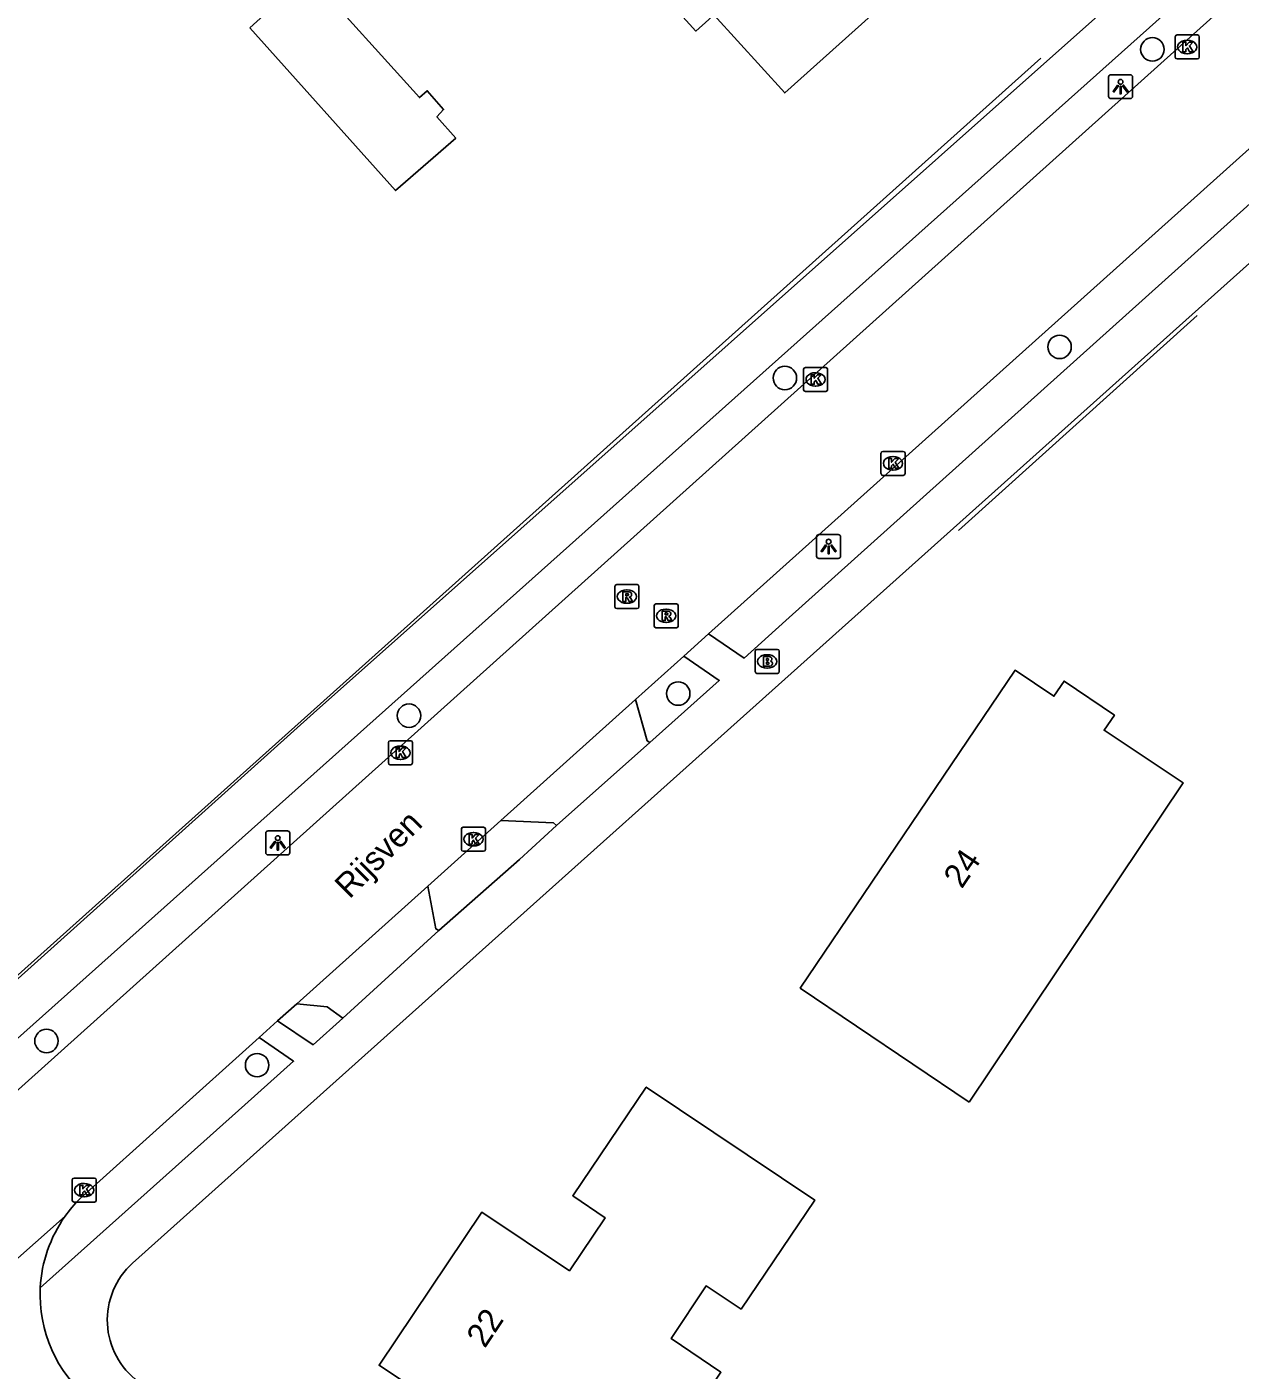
# Model space of a CAD drawing. Extents: x 163268 to 164360, y 381529 to 382285.
# Drawn here: x 163948.5 to 163999, y 381682.3 to 381738.3 of the extents above; entities that cross this region are included whole.
import ezdxf

# ---------------------------------------------------------------- set-up
doc = ezdxf.new("R2010")
doc.units = 0
for name, color, linetype in [('IMGEO_Boom', 7, 'Continuous'), ('IMGEO_Brandkraan', 7, 'Continuous'), ('IMGEO_Hek', 7, 'Continuous'), ('IMGEO_Kolk', 7, 'Continuous'), ('IMGEO_Lichtpunt', 7, 'Continuous'), ('IMGEO_Openbare_ruimte_label', 7, 'Continuous'), ('IMGEO_Pand', 7, 'Continuous'), ('IMGEO_Pand_nummerreeks', 7, 'Continuous'), ('IMGEO_Rijbaan_lokaal_open', 7, 'Continuous'), ('IMGEO_Rioolput', 7, 'Continuous'), ('IMGEO_Voetpad_open', 7, 'Continuous')]:
    doc.layers.add(name, color=color, linetype=linetype)

msp = doc.modelspace()

# ---------------------------------------------------------------- linework, layer by layer
at = {"layer": 'IMGEO_Boom'}
for centre in [(163995.384, 381737.33), (163991.517, 381724.931), (163980.071, 381723.636), (163975.628, 381710.482), (163964.412, 381709.563), (163949.308, 381696.004), (163958.082, 381694.996)]:
    msp.add_circle(centre, 0.489, dxfattribs=at)
at = {"layer": 'IMGEO_Brandkraan'}
for p, q in [((163978.835, 381711.397), (163978.835, 381712.249)), ((163978.91, 381712.323), (163979.762, 381712.323)), ((163979.323, 381712.103), (163979.348, 381712.103)), ((163979.836, 381712.249), (163979.836, 381711.397)), ((163979.346, 381711.543), (163979.321, 381711.543)), ((163979.762, 381711.323), (163978.91, 381711.323))]:
    msp.add_line(p, q, dxfattribs=at)
for points in [[(163978.835, 381711.397), (163978.835, 381712.249)], [(163978.91, 381712.323), (163979.762, 381712.323)], [(163979.183, 381712.023), (163979.183, 381711.623), (163979.396, 381711.623)], [(163979.414, 381712.023), (163979.183, 381712.023)], [(163979.836, 381712.249), (163979.836, 381711.397)], [(163979.362, 381711.942), (163979.308, 381711.942), (163979.308, 381711.866)], [(163979.308, 381711.866), (163979.361, 381711.866)], [(163979.37, 381711.79), (163979.308, 381711.79), (163979.308, 381711.709)], [(163979.308, 381711.709), (163979.37, 381711.709)], [(163979.762, 381711.323), (163978.91, 381711.323)]]:
    msp.add_lwpolyline(points, dxfattribs=at)
for centre, radius, start, end in [((163978.912, 381712.247), 0.0765, 91.552, 178.448), ((163978.912, 381712.247), 0.0765, 91.552, 178.448), ((163979.418, 381711.878), 0.145, 59.4692, 91.5367), ((163979.443, 381711.925), 0.0922, 285.5137, 58.1501), ((163979.76, 381712.247), 0.0765, 1.552, 88.448), ((163979.76, 381712.247), 0.0765, 1.552, 88.448), ((163978.912, 381711.399), 0.0765, 181.552, 268.448), ((163978.912, 381711.399), 0.0765, 181.552, 268.448), ((163979.363, 381711.904), 0.0379, 267.8285, 90.9355), ((163979.371, 381711.749), 0.0404, 269.8759, 90.5077), ((163979.402, 381711.874), 0.251, 268.6676, 293.5347), ((163979.448, 381711.733), 0.105, 301.3115, 78.989), ((163979.76, 381711.399), 0.0765, 271.552, 358.448), ((163979.76, 381711.399), 0.0765, 271.552, 358.448)]:
    msp.add_arc(centre, radius, start, end, dxfattribs=at)
for centre, major_axis, ratio, start_param, end_param in [((163979.322, 381711.823), (-0.387, 0.002), 0.722429, 4.712389, 7.853982), ((163979.347, 381711.823), (-0.39, 0.002), 0.717154, 1.570796, 4.712389)]:
    msp.add_ellipse(centre, major_axis=major_axis, ratio=ratio, start_param=start_param, end_param=end_param, dxfattribs=at)
at = {"layer": 'IMGEO_Hek'}
for points in [[(163924.002, 381677.14), (163990.733, 381736.967)], [(163987.306, 381717.275), (163997.245, 381726.234)]]:
    msp.add_lwpolyline(points, dxfattribs=at)
at = {"layer": 'IMGEO_Kolk'}
for p, q in [((163996.335, 381737.004), (163996.335, 381737.856)), ((163996.41, 381737.93), (163997.262, 381737.93)), ((163996.823, 381737.71), (163996.848, 381737.71)), ((163997.336, 381737.856), (163997.336, 381737.004)), ((163996.846, 381737.15), (163996.821, 381737.15)), ((163997.262, 381736.93), (163996.41, 381736.93)), ((163980.852, 381723.147), (163980.852, 381723.999)), ((163980.927, 381724.073), (163981.779, 381724.073)), ((163981.34, 381723.853), (163981.365, 381723.853)), ((163981.853, 381723.999), (163981.853, 381723.147)), ((163981.363, 381723.293), (163981.338, 381723.293)), ((163981.779, 381723.073), (163980.927, 381723.073)), ((163984.076, 381719.651), (163984.076, 381720.503)), ((163984.151, 381720.577), (163985.003, 381720.577)), ((163984.564, 381720.357), (163984.589, 381720.357)), ((163985.077, 381720.503), (163985.077, 381719.651)), ((163984.587, 381719.797), (163984.562, 381719.797)), ((163985.003, 381719.577), (163984.151, 381719.577)), ((163963.554, 381707.59), (163963.554, 381708.442)), ((163963.629, 381708.516), (163964.481, 381708.516)), ((163964.042, 381708.296), (163964.067, 381708.296)), ((163964.555, 381708.442), (163964.555, 381707.59)), ((163964.481, 381707.516), (163963.629, 381707.516)), ((163964.065, 381707.736), (163964.04, 381707.736)), ((163966.594, 381703.987), (163966.594, 381704.839)), ((163966.669, 381704.913), (163967.521, 381704.913)), ((163967.082, 381704.693), (163967.107, 381704.693)), ((163967.595, 381704.839), (163967.595, 381703.987)), ((163967.105, 381704.133), (163967.08, 381704.133)), ((163967.521, 381703.913), (163966.669, 381703.913)), ((163950.38, 381689.362), (163950.38, 381690.214)), ((163950.455, 381690.288), (163951.307, 381690.288)), ((163951.381, 381690.214), (163951.381, 381689.362)), ((163950.868, 381690.068), (163950.893, 381690.068)), ((163951.307, 381689.288), (163950.455, 381689.288)), ((163950.891, 381689.508), (163950.866, 381689.508))]:
    msp.add_line(p, q, dxfattribs=at)
for points in [[(163996.335, 381737.004), (163996.335, 381737.856)], [(163996.41, 381737.93), (163997.262, 381737.93)], [(163997.336, 381737.856), (163997.336, 381737.004)], [(163996.656, 381737.63), (163996.779, 381737.63), (163996.779, 381737.479), (163996.909, 381737.63), (163997.073, 381737.63), (163996.927, 381737.479), (163997.08, 381737.23), (163996.928, 381737.23), (163996.843, 381737.394), (163996.779, 381737.327), (163996.779, 381737.23), (163996.656, 381737.23), (163996.656, 381737.63)], [(163997.262, 381736.93), (163996.41, 381736.93)], [(163980.852, 381723.147), (163980.852, 381723.999)], [(163980.927, 381724.073), (163981.779, 381724.073)], [(163981.173, 381723.773), (163981.296, 381723.773), (163981.296, 381723.622), (163981.426, 381723.773), (163981.59, 381723.773), (163981.444, 381723.622), (163981.597, 381723.373), (163981.445, 381723.373), (163981.36, 381723.537), (163981.296, 381723.47), (163981.296, 381723.373), (163981.173, 381723.373), (163981.173, 381723.773)], [(163981.853, 381723.999), (163981.853, 381723.147)], [(163981.779, 381723.073), (163980.927, 381723.073)], [(163984.076, 381719.651), (163984.076, 381720.503)], [(163984.151, 381720.577), (163985.003, 381720.577)], [(163985.077, 381720.503), (163985.077, 381719.651)], [(163984.397, 381720.277), (163984.52, 381720.277), (163984.52, 381720.126), (163984.65, 381720.277), (163984.814, 381720.277), (163984.668, 381720.126), (163984.821, 381719.877), (163984.669, 381719.877), (163984.584, 381720.041), (163984.52, 381719.974), (163984.52, 381719.877), (163984.397, 381719.877), (163984.397, 381720.277)], [(163985.003, 381719.577), (163984.151, 381719.577)], [(163963.554, 381707.59), (163963.554, 381708.442)], [(163963.629, 381708.516), (163964.481, 381708.516)], [(163963.875, 381708.216), (163963.998, 381708.216), (163963.998, 381708.065), (163964.128, 381708.216), (163964.292, 381708.216), (163964.146, 381708.065), (163964.299, 381707.816), (163964.147, 381707.816), (163964.062, 381707.98), (163963.998, 381707.913), (163963.998, 381707.816), (163963.875, 381707.816), (163963.875, 381708.216)], [(163964.555, 381708.442), (163964.555, 381707.59)], [(163964.481, 381707.516), (163963.629, 381707.516)], [(163966.594, 381703.987), (163966.594, 381704.839)], [(163966.669, 381704.913), (163967.521, 381704.913)], [(163967.595, 381704.839), (163967.595, 381703.987)], [(163966.915, 381704.613), (163967.038, 381704.613), (163967.038, 381704.462), (163967.168, 381704.613), (163967.332, 381704.613), (163967.186, 381704.462), (163967.339, 381704.213), (163967.187, 381704.213), (163967.102, 381704.377), (163967.038, 381704.31), (163967.038, 381704.213), (163966.915, 381704.213), (163966.915, 381704.613)], [(163967.521, 381703.913), (163966.669, 381703.913)], [(163950.38, 381689.362), (163950.38, 381690.214)], [(163950.455, 381690.288), (163951.307, 381690.288)], [(163951.381, 381690.214), (163951.381, 381689.362)], [(163950.701, 381689.988), (163950.824, 381689.988), (163950.824, 381689.837), (163950.954, 381689.988), (163951.118, 381689.988), (163950.972, 381689.837), (163951.125, 381689.588), (163950.973, 381689.588), (163950.888, 381689.752), (163950.824, 381689.685), (163950.824, 381689.588), (163950.701, 381689.588), (163950.701, 381689.988)], [(163951.307, 381689.288), (163950.455, 381689.288)]]:
    msp.add_lwpolyline(points, dxfattribs=at)
for centre, start, end in [((163996.412, 381737.854), 91.552, 178.448), ((163996.412, 381737.854), 91.552, 178.448), ((163997.26, 381737.854), 1.552, 88.448), ((163997.26, 381737.854), 1.552, 88.448), ((163996.412, 381737.006), 181.552, 268.448), ((163996.412, 381737.006), 181.552, 268.448), ((163997.26, 381737.006), 271.552, 358.448), ((163997.26, 381737.006), 271.552, 358.448), ((163980.929, 381723.997), 91.552, 178.448), ((163980.929, 381723.997), 91.552, 178.448), ((163981.777, 381723.997), 1.552, 88.448), ((163981.777, 381723.997), 1.552, 88.448), ((163980.929, 381723.149), 181.552, 268.448), ((163980.929, 381723.149), 181.552, 268.448), ((163981.777, 381723.149), 271.552, 358.448), ((163981.777, 381723.149), 271.552, 358.448), ((163984.153, 381720.501), 91.552, 178.448), ((163984.153, 381720.501), 91.552, 178.448), ((163985.001, 381720.501), 1.552, 88.448), ((163985.001, 381720.501), 1.552, 88.448), ((163984.153, 381719.653), 181.552, 268.448), ((163984.153, 381719.653), 181.552, 268.448), ((163985.001, 381719.653), 271.552, 358.448), ((163985.001, 381719.653), 271.552, 358.448), ((163963.631, 381708.44), 91.552, 178.448), ((163963.631, 381708.44), 91.552, 178.448), ((163964.479, 381708.44), 1.552, 88.448), ((163964.479, 381708.44), 1.552, 88.448), ((163963.631, 381707.592), 181.552, 268.448), ((163963.631, 381707.592), 181.552, 268.448), ((163964.479, 381707.592), 271.552, 358.448), ((163964.479, 381707.592), 271.552, 358.448), ((163966.671, 381704.837), 91.552, 178.448), ((163966.671, 381704.837), 91.552, 178.448), ((163967.519, 381704.837), 1.552, 88.448), ((163967.519, 381704.837), 1.552, 88.448), ((163966.671, 381703.989), 181.552, 268.448), ((163966.671, 381703.989), 181.552, 268.448), ((163967.519, 381703.989), 271.552, 358.448), ((163967.519, 381703.989), 271.552, 358.448), ((163950.457, 381690.212), 91.552, 178.448), ((163950.457, 381690.212), 91.552, 178.448), ((163951.305, 381690.212), 1.552, 88.448), ((163951.305, 381690.212), 1.552, 88.448), ((163950.457, 381689.364), 181.552, 268.448), ((163950.457, 381689.364), 181.552, 268.448), ((163951.305, 381689.364), 271.552, 358.448), ((163951.305, 381689.364), 271.552, 358.448)]:
    msp.add_arc(centre, 0.0765, start, end, dxfattribs=at)
for centre, major_axis, ratio, start_param, end_param in [((163996.822, 381737.43), (-0.387, 0.002), 0.722429, 4.712389, 7.853982), ((163996.847, 381737.43), (-0.39, 0.002), 0.717154, 1.570796, 4.712389), ((163981.339, 381723.573), (-0.387, 0.002), 0.722429, 4.712389, 7.853982), ((163981.364, 381723.573), (-0.39, 0.002), 0.717154, 1.570796, 4.712389), ((163984.563, 381720.077), (-0.387, 0.002), 0.722429, 4.712389, 7.853982), ((163984.588, 381720.077), (-0.39, 0.002), 0.717154, 1.570796, 4.712389), ((163964.041, 381708.016), (-0.387, 0.002), 0.722429, 4.712389, 7.853982), ((163964.066, 381708.016), (-0.39, 0.002), 0.717154, 1.570796, 4.712389), ((163967.081, 381704.413), (-0.387, 0.002), 0.722429, 4.712389, 7.853982), ((163967.106, 381704.413), (-0.39, 0.002), 0.717154, 1.570796, 4.712389), ((163950.867, 381689.788), (-0.387, 0.002), 0.722429, 4.712389, 7.853982), ((163950.892, 381689.788), (-0.39, 0.002), 0.717154, 1.570796, 4.712389)]:
    msp.add_ellipse(centre, major_axis=major_axis, ratio=ratio, start_param=start_param, end_param=end_param, dxfattribs=at)
at = {"layer": 'IMGEO_Lichtpunt'}
for p, q in [((163993.559, 381736.18), (163993.559, 381735.373)), ((163993.559, 381736.18), (163993.559, 381735.373)), ((163994.461, 381736.275), (163993.653, 381736.275)), ((163994.461, 381736.275), (163993.653, 381736.275)), ((163994.555, 381735.373), (163994.555, 381736.18)), ((163994.555, 381735.373), (163994.555, 381736.18)), ((163993.653, 381735.279), (163994.461, 381735.279)), ((163993.653, 381735.279), (163994.461, 381735.279)), ((163981.396, 381717.016), (163981.396, 381716.209)), ((163981.396, 381717.016), (163981.396, 381716.209)), ((163982.298, 381717.111), (163981.49, 381717.111)), ((163982.298, 381717.111), (163981.49, 381717.111)), ((163982.392, 381716.209), (163982.392, 381717.016)), ((163982.392, 381716.209), (163982.392, 381717.016)), ((163981.49, 381716.115), (163982.298, 381716.115)), ((163981.49, 381716.115), (163982.298, 381716.115)), ((163959.347, 381704.758), (163958.539, 381704.758)), ((163959.347, 381704.758), (163958.539, 381704.758)), ((163958.445, 381704.663), (163958.445, 381703.856)), ((163958.445, 381704.663), (163958.445, 381703.856)), ((163959.441, 381703.856), (163959.441, 381704.663)), ((163959.441, 381703.856), (163959.441, 381704.663)), ((163958.539, 381703.762), (163959.347, 381703.762)), ((163958.539, 381703.762), (163959.347, 381703.762))]:
    msp.add_line(p, q, dxfattribs=at)
for points in [[(163993.933, 381735.844), (163993.972, 381735.816), (163993.784, 381735.554), (163993.746, 381735.581), (163993.933, 381735.844)], [(163994.035, 381735.796), (163994.082, 381735.796), (163994.082, 381735.474), (163994.035, 381735.474), (163994.035, 381735.796)], [(163994.145, 381735.816), (163994.183, 381735.843), (163994.37, 381735.581), (163994.331, 381735.553), (163994.145, 381735.816)], [(163981.77, 381716.68), (163981.809, 381716.652), (163981.621, 381716.39), (163981.583, 381716.417), (163981.77, 381716.68)], [(163981.872, 381716.632), (163981.919, 381716.632), (163981.919, 381716.31), (163981.872, 381716.31), (163981.872, 381716.632)], [(163981.982, 381716.652), (163982.02, 381716.679), (163982.207, 381716.417), (163982.168, 381716.389), (163981.982, 381716.652)], [(163958.819, 381704.327), (163958.858, 381704.299), (163958.67, 381704.037), (163958.632, 381704.064), (163958.819, 381704.327)], [(163958.921, 381704.279), (163958.968, 381704.279), (163958.968, 381703.957), (163958.921, 381703.957), (163958.921, 381704.279)], [(163959.031, 381704.299), (163959.069, 381704.326), (163959.256, 381704.064), (163959.217, 381704.036), (163959.031, 381704.299)]]:
    msp.add_lwpolyline(points, dxfattribs=at)
for centre in [(163994.058, 381735.978), (163981.895, 381716.814), (163958.944, 381704.461)]:
    msp.add_circle(centre, 0.0994, dxfattribs=at)
for centre, start, end in [((163993.653, 381736.18), 90, 180), ((163993.653, 381736.18), 90, 180), ((163994.461, 381736.18), 0, 90), ((163994.461, 381736.18), 0, 90), ((163993.653, 381735.373), 180, 270), ((163993.653, 381735.373), 180, 270), ((163994.461, 381735.373), 270, 0), ((163994.461, 381735.373), 270, 360), ((163981.49, 381717.016), 90, 180), ((163981.49, 381717.016), 90, 180), ((163982.298, 381717.016), 0, 90), ((163982.298, 381717.016), 0, 90), ((163981.49, 381716.209), 180, 270), ((163981.49, 381716.209), 180, 270), ((163982.298, 381716.209), 270, 0), ((163982.298, 381716.209), 270, 360), ((163958.539, 381704.663), 90, 180), ((163958.539, 381704.663), 90, 180), ((163959.347, 381704.663), 0, 90), ((163959.347, 381704.663), 0, 90), ((163958.539, 381703.856), 180, 270), ((163958.539, 381703.856), 180, 270), ((163959.347, 381703.856), 270, 0), ((163959.347, 381703.856), 270, 360)]:
    msp.add_arc(centre, 0.0946, start, end, dxfattribs=at)
at = {"layer": 'IMGEO_Pand'}
for points in [[(163979.064, 381754.234), (163983.233, 381749.598), (163984.57, 381748.111), (163985.554, 381748.969), (163989.791, 381744.248), (163980.063, 381735.515), (163977.118, 381738.774), (163976.899, 381738.577), (163976.361, 381738.091), (163974.092, 381740.608), (163974.62, 381741.084), (163974.849, 381741.291), (163974.416, 381741.778), (163977.13, 381744.283), (163973.47, 381748.297), (163972.999, 381748.813), (163979.064, 381754.234)], [(163957.785, 381738.222), (163960.225, 381740.447), (163964.847, 381735.323), (163965.172, 381735.604), (163965.852, 381734.818), (163965.574, 381734.523), (163966.36, 381733.631), (163963.849, 381731.446), (163957.785, 381738.222)], [(163987.751, 381693.45), (163996.66, 381706.764), (163993.374, 381708.951), (163993.8, 381709.58), (163991.702, 381711.002), (163991.279, 381710.373), (163989.664, 381711.458), (163980.709, 381698.211), (163987.751, 381693.45)], [(163971.601, 381675.605), (163972.165, 381676.431), (163973.105, 381675.811), (163977.407, 381682.198), (163975.332, 381683.611), (163976.789, 381685.794), (163978.249, 381684.83), (163981.316, 381689.371), (163974.293, 381694.081), (163971.232, 381689.552), (163972.591, 381688.633), (163971.094, 381686.43), (163967.447, 381688.874), (163963.166, 381682.487), (163969.41, 381678.312), (163968.851, 381677.482), (163971.601, 381675.605)]]:
    msp.add_lwpolyline(points, dxfattribs=at)
at = {"layer": 'IMGEO_Rijbaan_lokaal_open'}
for points in [[(163997.915, 381738.698), (163942.403, 381688.848)], [(163976.894, 381712.972), (164001.298, 381734.874)], [(163976.894, 381712.972), (163975.86, 381712.042)], [(163973.846, 381710.232), (163975.86, 381712.042)], [(163968.237, 381705.192), (163973.846, 381710.232)], [(163965.19, 381702.454), (163968.237, 381705.192)], [(163959.732, 381697.549), (163965.19, 381702.454)], [(163958.939, 381696.837), (163959.732, 381697.549)], [(163958.939, 381696.837), (163958.169, 381696.144)], [(163958.169, 381696.144), (163950.696, 381689.429)], [(163950.08, 381688.697), (163939.322, 381679.159)]]:
    msp.add_lwpolyline(points, dxfattribs=at)
for centre, radius, start, end in [((163954.791, 381685.358), 5.774, 135.1666, 144.6702), ((163954.711, 381685.428), 5.669, 144.781, 177.0254), ((163954.717, 381685.427), 5.675, 177.0228, 230.5836)]:
    msp.add_arc(centre, radius, start, end, dxfattribs=at)
at = {"layer": 'IMGEO_Rioolput'}
for p, q in [((163972.99, 381714.099), (163972.99, 381714.951)), ((163973.065, 381715.025), (163973.917, 381715.025)), ((163973.478, 381714.805), (163973.503, 381714.805)), ((163973.991, 381714.951), (163973.991, 381714.099)), ((163973.501, 381714.245), (163973.476, 381714.245)), ((163974.701, 381714.223), (163975.553, 381714.223)), ((163973.917, 381714.025), (163973.065, 381714.025)), ((163974.626, 381713.297), (163974.626, 381714.149)), ((163975.114, 381714.003), (163975.139, 381714.003)), ((163975.627, 381714.149), (163975.627, 381713.297)), ((163975.553, 381713.223), (163974.701, 381713.223)), ((163975.137, 381713.443), (163975.112, 381713.443))]:
    msp.add_line(p, q, dxfattribs=at)
for points in [[(163972.99, 381714.099), (163972.99, 381714.951)], [(163973.065, 381715.025), (163973.917, 381715.025)], [(163973.991, 381714.951), (163973.991, 381714.099)], [(163973.579, 381714.723), (163973.327, 381714.725), (163973.327, 381714.325)], [(163973.327, 381714.325), (163973.451, 381714.325), (163973.451, 381714.487), (163973.462, 381714.487)], [(163973.505, 381714.644), (163973.451, 381714.644), (163973.451, 381714.563)], [(163973.451, 381714.563), (163973.503, 381714.563)], [(163973.509, 381714.458), (163973.58, 381714.325), (163973.72, 381714.325), (163973.655, 381714.451)], [(163974.701, 381714.223), (163975.553, 381714.223)], [(163973.917, 381714.025), (163973.065, 381714.025)], [(163974.626, 381713.297), (163974.626, 381714.149)], [(163975.215, 381713.921), (163974.963, 381713.923), (163974.963, 381713.523)], [(163974.963, 381713.523), (163975.087, 381713.523), (163975.087, 381713.685), (163975.098, 381713.685)], [(163975.141, 381713.842), (163975.087, 381713.842), (163975.087, 381713.761)], [(163975.087, 381713.761), (163975.139, 381713.761)], [(163975.145, 381713.656), (163975.216, 381713.523), (163975.356, 381713.523), (163975.291, 381713.649)], [(163975.627, 381714.149), (163975.627, 381713.297)], [(163975.553, 381713.223), (163974.701, 381713.223)]]:
    msp.add_lwpolyline(points, dxfattribs=at)
for centre, radius, start, end in [((163973.067, 381714.949), 0.0765, 91.552, 178.448), ((163973.067, 381714.949), 0.0765, 91.552, 178.448), ((163973.915, 381714.949), 0.0765, 1.552, 88.448), ((163973.915, 381714.949), 0.0765, 1.552, 88.448), ((163973.461, 381714.434), 0.0533, 26.0293, 88.6989), ((163973.487, 381714.752), 0.19, 274.7715, 282.9687), ((163973.511, 381714.548), 0.0964, 77.0061, 93.1865), ((163973.525, 381714.605), 0.0378, 276.6634, 79.6772), ((163973.578, 381714.613), 0.109, 350.3612, 89.416), ((163973.576, 381714.613), 0.112, 277.5842, 350.9817), ((163973.56, 381714.398), 0.108, 29.5134, 73.7905), ((163974.703, 381714.147), 0.0765, 91.552, 178.448), ((163974.703, 381714.147), 0.0765, 91.552, 178.448), ((163975.551, 381714.147), 0.0765, 1.552, 88.448), ((163975.551, 381714.147), 0.0765, 1.552, 88.448), ((163973.067, 381714.101), 0.0765, 181.552, 268.448), ((163973.067, 381714.101), 0.0765, 181.552, 268.448), ((163973.915, 381714.101), 0.0765, 271.552, 358.448), ((163973.915, 381714.101), 0.0765, 271.552, 358.448), ((163975.097, 381713.632), 0.0533, 26.0293, 88.6989), ((163975.123, 381713.95), 0.19, 274.7715, 282.9687), ((163975.147, 381713.746), 0.0964, 77.0061, 93.1865), ((163975.161, 381713.803), 0.0378, 276.6634, 79.6772), ((163975.214, 381713.811), 0.109, 350.3612, 89.416), ((163975.212, 381713.811), 0.112, 277.5842, 350.9817), ((163975.196, 381713.596), 0.108, 29.5134, 73.7905), ((163974.703, 381713.299), 0.0765, 181.552, 268.448), ((163974.703, 381713.299), 0.0765, 181.552, 268.448), ((163975.551, 381713.299), 0.0765, 271.552, 358.448), ((163975.551, 381713.299), 0.0765, 271.552, 358.448)]:
    msp.add_arc(centre, radius, start, end, dxfattribs=at)
for centre, major_axis, ratio, start_param, end_param in [((163973.477, 381714.525), (-0.387, 0.002), 0.722429, 4.712389, 7.853982), ((163973.502, 381714.525), (-0.39, 0.002), 0.717154, 1.570796, 4.712389), ((163975.113, 381713.723), (-0.387, 0.002), 0.722429, 4.712389, 7.853982), ((163975.138, 381713.723), (-0.39, 0.002), 0.717154, 1.570796, 4.712389)]:
    msp.add_ellipse(centre, major_axis=major_axis, ratio=ratio, start_param=start_param, end_param=end_param, dxfattribs=at)
at = {"layer": 'IMGEO_Voetpad_open'}
for points in [[(163907.846, 381662.609), (163917.878, 381671.183), (163917.751, 381671.321), (163960.431, 381709.666), (163995.111, 381740.522)], [(163942.403, 381688.848), (163941.316, 381690.061), (163942.506, 381691.118), (163996.309, 381739.168), (163996.732, 381739.613), (163996.909, 381739.831)], [(164002.462, 381733.6), (164000.815, 381732.134), (163980.105, 381713.523), (163978.377, 381711.96), (163976.894, 381712.972)], [(163952.896, 381686.744), (164004.063, 381732.568)], [(163975.86, 381712.042), (163977.34, 381711.03), (163974.445, 381708.442)], [(163973.846, 381710.232), (163974.332, 381708.518), (163974.445, 381708.442)], [(163974.445, 381708.442), (163970.557, 381704.984)], [(163970.557, 381704.984), (163969.011, 381703.561), (163965.655, 381700.603)], [(163970.557, 381704.984), (163970.427, 381705.096), (163968.237, 381705.192)], [(163965.19, 381702.454), (163965.531, 381700.673), (163965.655, 381700.603)], [(163965.655, 381700.603), (163961.653, 381696.958)], [(163961.653, 381696.958), (163961.008, 381697.433), (163959.732, 381697.549)], [(163961.653, 381696.958), (163960.423, 381695.845), (163958.939, 381696.837)], [(163949.05, 381685.722), (163957.577, 381693.337), (163959.605, 381695.159), (163958.169, 381696.144)]]:
    msp.add_lwpolyline(points, dxfattribs=at)
msp.add_arc((163955.034, 381684.374), 3.192, 132.0519, 233.6046, dxfattribs=at)

# ---------------------------------------------------------------- texts
at = {"layer": 'IMGEO_Openbare_ruimte_label'}
msp.add_text('Rijsven', height=1, rotation=45.0405, dxfattribs=at).set_placement((163961.931, 381701.895))
at = {"layer": 'IMGEO_Pand_nummerreeks'}
for s, rotation, p in [('24', 55.9423, (163987.443, 381702.315)), ('22', 56.1689, (163967.569, 381683.165))]:
    msp.add_text(s, height=1, rotation=rotation, dxfattribs=at).set_placement(p)

doc.saveas('drawing.dxf')
